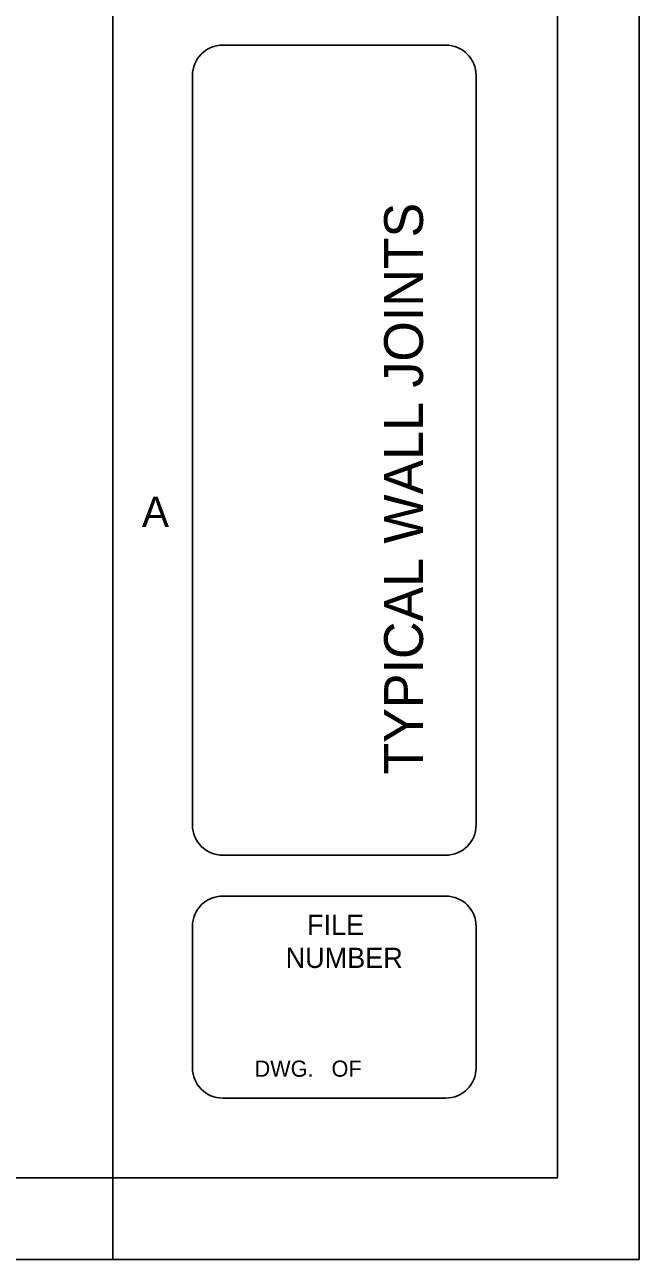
# Model space of a CAD drawing. Extents: x 22369.6 to 22428.3, y 22369.6 to 22415.
# Drawn here: x 22423.23 to 22428.29, y 22369.62 to 22379.79 of the extents above; entities that cross this region are included whole.
import ezdxf

# ---------------------------------------------------------------- set-up
doc = ezdxf.new("R2010")
doc.units = 0
for name, color, linetype in [('Level 1', 7, 'Continuous'), ('Level 10', 7, 'Continuous'), ('Level 2', 7, 'Continuous'), ('Level 3', 7, 'Continuous'), ('Level 9', 7, 'Continuous')]:
    doc.layers.add(name, color=color, linetype=linetype)

msp = doc.modelspace()

# ---------------------------------------------------------------- linework, layer by layer
at = {"layer": 'Level 1'}
for p, q in [((22424.858, 22372.949), (22426.694, 22372.949)), ((22424.858, 22372.613), (22426.694, 22372.613)), ((22424.858, 22370.949), (22426.694, 22370.949)), ((22423.536, 22370.293), (22424.208, 22370.293))]:
    msp.add_line(p, q, dxfattribs=at)
msp.add_lwpolyline([(22369.621, 22414.965), (22428.288, 22414.965), (22428.288, 22369.621), (22369.621, 22369.621)], close=True, dxfattribs=at)
for points in [[(22424.858, 22379.621), (22426.694, 22379.621)], [(22424.608, 22373.199), (22424.608, 22379.371)], [(22426.944, 22373.199), (22426.944, 22379.371)], [(22424.608, 22371.199), (22424.608, 22372.363)], [(22426.944, 22372.363), (22426.944, 22371.199)]]:
    msp.add_lwpolyline(points, dxfattribs=at)
for centre, start, end in [((22424.858, 22379.371), 90, 180), ((22426.694, 22379.371), 0, 90), ((22424.858, 22373.199), 180, 270), ((22426.694, 22373.199), 270, 0), ((22424.858, 22372.363), 90, 180), ((22426.694, 22372.363), 0, 90), ((22424.858, 22371.199), 180, 270), ((22426.694, 22371.199), 270, 0)]:
    msp.add_arc(centre, 0.25, start, end, dxfattribs=at)
at = {"layer": 'Level 10'}
msp.add_line((22423.952, 22369.621), (22423.952, 22370.293), dxfattribs=at)
at = {"layer": 'Level 9'}
for p, q in [((22427.616, 22370.293), (22427.616, 22414.293)), ((22371.621, 22370.293), (22423.952, 22370.293)), ((22423.952, 22370.293), (22427.616, 22370.293))]:
    msp.add_line(p, q, dxfattribs=at)
msp.add_lwpolyline([(22423.952, 22370.293), (22423.952, 22414.293)], dxfattribs=at)

# ---------------------------------------------------------------- texts
at = {"layer": 'Level 1'}
msp.add_text('A', height=0.25, dxfattribs=at).set_placement((22424.192, 22375.653))
at = {"layer": 'Level 2'}
for s, height, p in [('FILE', 0.1664, (22425.552, 22372.293)), ('NUMBER', 0.1664, (22425.376, 22372.021)), ('DWG.   OF  ', 0.13334, (22425.12, 22371.125))]:
    msp.add_text(s, height=height, dxfattribs=at).set_placement(p)
at = {"layer": 'Level 3'}
msp.add_text('TYPICAL WALL JOINTS', height=0.32, rotation=90, dxfattribs=at).set_placement((22426.507, 22373.614))

doc.saveas('drawing.dxf')
